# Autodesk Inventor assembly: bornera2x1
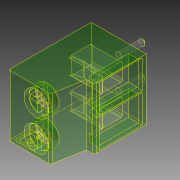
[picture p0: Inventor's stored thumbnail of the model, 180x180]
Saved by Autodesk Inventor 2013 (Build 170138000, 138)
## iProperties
Created: 2021-02
Part Number: bornera2x1
Document SubType Name: Assembly
Designer: Fede
Author: Fede
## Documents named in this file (2)
- C:\0000 FEDE\16GB\0000 INTERIOR\DE_TMP_BAS\BAS_DTON - demora conexion al energizar\pcb\BOR\turn on\Imported Components\BAS_DTON\bornera2x1.iam
- C:\0000 FEDE\16GB\0000 INTERIOR\DE_TMP_BAS\BAS_DTON - demora conexion al energizar\pcb\BOR\turn on\Imported Components\BAS_DTON\bornera2x1.ipt
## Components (1 placed, 1 different names)
1. bornera2x1:1
